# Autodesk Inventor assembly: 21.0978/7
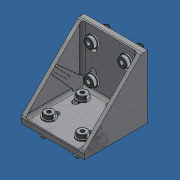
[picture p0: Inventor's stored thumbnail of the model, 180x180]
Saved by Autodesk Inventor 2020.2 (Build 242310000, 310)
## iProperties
Created: 2012-01
Part Number: 21.0978/7
Document SubType Name: Assembly
Designer: Administrator
Mass: 513.478 g
Surface Area: 619.894 cm^2
Volume: 152.472 cm^3
Density: 3.36769 g/cm^3
Description: ANGLE 90 POS FXG
Author: Administrator
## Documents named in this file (5)
- Y:\INVENTOR LIBRARIES\PARTS LIBRARY\FASTENING ELEMENTS\21.0978_7 ANGLE 90 POS FXG.iam
- Y:\INVENTOR LIBRARIES\PARTS LIBRARY\FASTENING ELEMENTS\SUBCOMPONENTS\21.0978_2 ANGLE 90.ipt
- Y:\INVENTOR LIBRARIES\PARTS LIBRARY\FASTENING ELEMENTS\SCREWS CAP\21.1280 M8X22.ipt
- Y:\INVENTOR LIBRARIES\PARTS LIBRARY\FASTENING ELEMENTS\WASHERS\21.1127 M8 ROUND WASHER.ipt
- Y:\INVENTOR LIBRARIES\PARTS LIBRARY\FASTENING ELEMENTS\NUTS\21.1351_2 M8 SQUARE NUT POS FXG.ipt
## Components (25 placed, 4 different names)
1. 21.0978_2 ANGLE 90:1 — Mate:1, Mate:2, Mate:3, Mate:4, Mate:5, Mate:6, Mate:7, Mate:8, Mate:9, Mate:10, Mate:11, Mate:12, Mate:13, Mate:14, Mate:15, Mate:16, Mate:17, Mate:18, Mate:19, Mate:20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
2. 21.1280 M8X22:1 — Insert:7, Mate:12, Mate:19, Mate:28
3. 21.1280 M8X22:2 — Insert:8, Mate:9, Mate:17, Mate:26
4. 21.1280 M8X22:3 — Insert:1, Mate:10, Mate:18, Mate:25
5. 21.1280 M8X22:4 — Insert:2, Mate:11, Mate:20, Mate:27
6. 21.1280 M8X22:5 — Insert:3, Mate:16, Mate:21, Mate:32
7. 21.1280 M8X22:6 — Insert:4, Mate:15, Mate:22, Mate:30
8. 21.1280 M8X22:7 — Insert:6, Mate:14, Mate:23, Mate:31
9. 21.1280 M8X22:8 — Insert:5, Mate:13, Mate:24, Mate:29
10. 21.1127 WASHER M8:1 — Insert:5, Mate:8
11. 21.1127 WASHER M8:2 — Insert:6, Mate:7
12. 21.1127 WASHER M8:3 — Insert:7, Mate:3
13. 21.1127 WASHER M8:4 — Insert:8, Mate:2
14. 21.1127 WASHER M8:5 — Insert:4, Mate:6
15. 21.1127 WASHER M8:6 — Insert:3, Mate:5
16. 21.1127 WASHER M8:7 — Insert:2, Mate:4
17. 21.1127 WASHER M8:8 — Insert:1, Mate:1
18. 21.1351_2 M8 SQUARE NUT POS FXG:1 — Mate:29, Mate:35, Angle:2
19. 21.1351_2 M8 SQUARE NUT POS FXG:2 — Mate:31, Mate:36, Angle:1
20. 21.1351_2 M8 SQUARE NUT POS FXG:3 — Mate:30, Mate:34, Angle:12
21. 21.1351_2 M8 SQUARE NUT POS FXG:4 — Mate:32, Mate:33, Angle:11
22. 21.1351_2 M8 SQUARE NUT POS FXG:5 — Mate:26, Mate:40, Angle:7
23. 21.1351_2 M8 SQUARE NUT POS FXG:6 — Mate:25, Mate:39, Angle:8
24. 21.1351_2 M8 SQUARE NUT POS FXG:7 — Mate:27, Mate:37, Angle:9
25. 21.1351_2 M8 SQUARE NUT POS FXG:8 — Mate:28, Mate:38, Angle:10
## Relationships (56: Mate 40, Insert 8, Angle 8)
- Insert:1: 21.1280 M8X22:3 ↔ 21.1127 WASHER M8:8
- Insert:2: 21.1280 M8X22:4 ↔ 21.1127 WASHER M8:7
- Insert:3: 21.1280 M8X22:5 ↔ 21.1127 WASHER M8:6
- Insert:4: 21.1280 M8X22:6 ↔ 21.1127 WASHER M8:5
- Insert:5: 21.1280 M8X22:8 ↔ 21.1127 WASHER M8:1
- Insert:6: 21.1280 M8X22:7 ↔ 21.1127 WASHER M8:2
- Insert:7: 21.1280 M8X22:1 ↔ 21.1127 WASHER M8:3
- Insert:8: 21.1280 M8X22:2 ↔ 21.1127 WASHER M8:4
- Mate:1: 21.0978_2 ANGLE 90:1 ↔ 21.1127 WASHER M8:8
- Mate:2: 21.0978_2 ANGLE 90:1 ↔ 21.1127 WASHER M8:4
- Mate:3: 21.0978_2 ANGLE 90:1 ↔ 21.1127 WASHER M8:3
- Mate:4: 21.0978_2 ANGLE 90:1 ↔ 21.1127 WASHER M8:7
- Mate:5: 21.0978_2 ANGLE 90:1 ↔ 21.1127 WASHER M8:6
- Mate:6: 21.0978_2 ANGLE 90:1 ↔ 21.1127 WASHER M8:5
- Mate:7: 21.0978_2 ANGLE 90:1 ↔ 21.1127 WASHER M8:2
- Mate:8: 21.0978_2 ANGLE 90:1 ↔ 21.1127 WASHER M8:1
- Mate:9: 21.0978_2 ANGLE 90:1 ↔ 21.1280 M8X22:2
- Mate:10: 21.0978_2 ANGLE 90:1 ↔ 21.1280 M8X22:3
- Mate:11: 21.0978_2 ANGLE 90:1 ↔ 21.1280 M8X22:4
- Mate:12: 21.0978_2 ANGLE 90:1 ↔ 21.1280 M8X22:1
- Mate:13: 21.0978_2 ANGLE 90:1 ↔ 21.1280 M8X22:8
- Mate:14: 21.0978_2 ANGLE 90:1 ↔ 21.1280 M8X22:7
- Mate:15: 21.0978_2 ANGLE 90:1 ↔ 21.1280 M8X22:6
- Mate:16: 21.0978_2 ANGLE 90:1 ↔ 21.1280 M8X22:5
- Mate:17: 21.0978_2 ANGLE 90:1 ↔ 21.1280 M8X22:2
- Mate:18: 21.0978_2 ANGLE 90:1 ↔ 21.1280 M8X22:3
- Mate:19: 21.0978_2 ANGLE 90:1 ↔ 21.1280 M8X22:1
- Mate:20: 21.0978_2 ANGLE 90:1 ↔ 21.1280 M8X22:4
- Mate:21: 21.0978_2 ANGLE 90:1 ↔ 21.1280 M8X22:5
- Mate:22: 21.0978_2 ANGLE 90:1 ↔ 21.1280 M8X22:6
- Mate:23: 21.0978_2 ANGLE 90:1 ↔ 21.1280 M8X22:7
- Mate:24: 21.0978_2 ANGLE 90:1 ↔ 21.1280 M8X22:8
- Mate:25: 21.1280 M8X22:3 ↔ 21.1351_2 M8 SQUARE NUT POS FXG:6
- Mate:26: 21.1280 M8X22:2 ↔ 21.1351_2 M8 SQUARE NUT POS FXG:5
- Mate:27: 21.1280 M8X22:4 ↔ 21.1351_2 M8 SQUARE NUT POS FXG:7
- Mate:28: 21.1280 M8X22:1 ↔ 21.1351_2 M8 SQUARE NUT POS FXG:8
- Mate:29: 21.1280 M8X22:8 ↔ 21.1351_2 M8 SQUARE NUT POS FXG:1
- Mate:30: 21.1280 M8X22:6 ↔ 21.1351_2 M8 SQUARE NUT POS FXG:3
- Mate:31: 21.1280 M8X22:7 ↔ 21.1351_2 M8 SQUARE NUT POS FXG:2
- Mate:32: 21.1280 M8X22:5 ↔ 21.1351_2 M8 SQUARE NUT POS FXG:4
- Mate:33: 21.0978_2 ANGLE 90:1 ↔ 21.1351_2 M8 SQUARE NUT POS FXG:4
- Mate:34: 21.0978_2 ANGLE 90:1 ↔ 21.1351_2 M8 SQUARE NUT POS FXG:3
- Mate:35: 21.0978_2 ANGLE 90:1 ↔ 21.1351_2 M8 SQUARE NUT POS FXG:1
- Mate:36: 21.0978_2 ANGLE 90:1 ↔ 21.1351_2 M8 SQUARE NUT POS FXG:2
- Angle:1: 21.0978_2 ANGLE 90:1 ↔ 21.1351_2 M8 SQUARE NUT POS FXG:2
- Angle:2: 21.0978_2 ANGLE 90:1 ↔ 21.1351_2 M8 SQUARE NUT POS FXG:1
- Mate:37: 21.0978_2 ANGLE 90:1 ↔ 21.1351_2 M8 SQUARE NUT POS FXG:7
- Mate:38: 21.0978_2 ANGLE 90:1 ↔ 21.1351_2 M8 SQUARE NUT POS FXG:8
- Mate:39: 21.0978_2 ANGLE 90:1 ↔ 21.1351_2 M8 SQUARE NUT POS FXG:6
- Mate:40: 21.0978_2 ANGLE 90:1 ↔ 21.1351_2 M8 SQUARE NUT POS FXG:5
- Angle:7: 21.0978_2 ANGLE 90:1 ↔ 21.1351_2 M8 SQUARE NUT POS FXG:5
- Angle:8: 21.0978_2 ANGLE 90:1 ↔ 21.1351_2 M8 SQUARE NUT POS FXG:6
- Angle:9: 21.0978_2 ANGLE 90:1 ↔ 21.1351_2 M8 SQUARE NUT POS FXG:7
- Angle:10: 21.0978_2 ANGLE 90:1 ↔ 21.1351_2 M8 SQUARE NUT POS FXG:8
- Angle:11: 21.0978_2 ANGLE 90:1 ↔ 21.1351_2 M8 SQUARE NUT POS FXG:4
- Angle:12: 21.0978_2 ANGLE 90:1 ↔ 21.1351_2 M8 SQUARE NUT POS FXG:3
